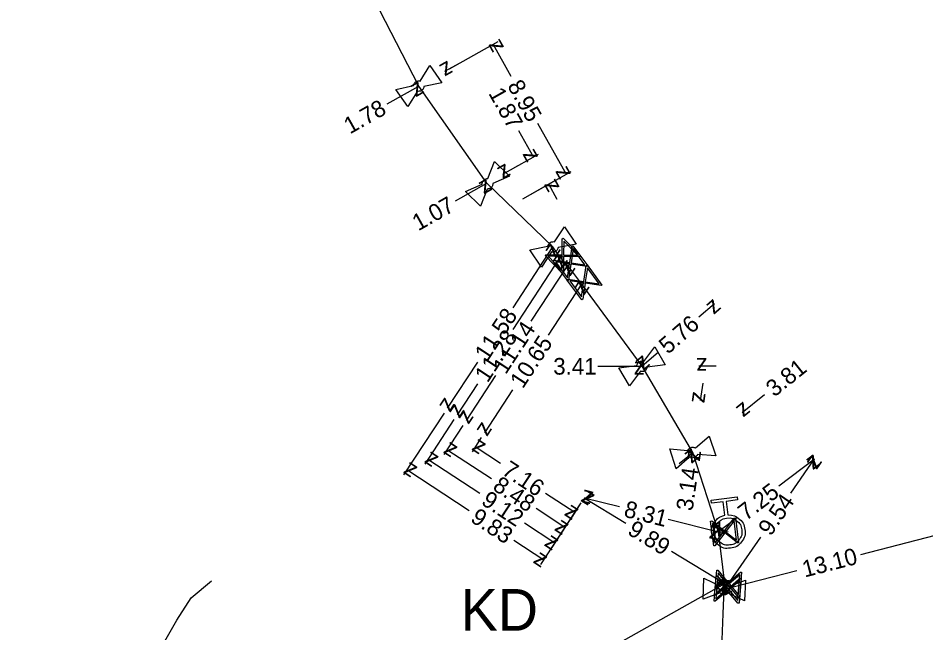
# Model space of a CAD drawing. Extents: x -638315 to -636370, y -1116147 to -1115110.
# Drawn here: x -637130.1 to -637075.6, y -1115916.4 to -1115879.5 of the extents above; entities that cross this region are included whole.
import ezdxf

# ---------------------------------------------------------------- set-up
doc = ezdxf.new("R2010")
doc.units = 0
for name, color, linetype in [('Default', 7, 'Continuous'), ('VP Hydrant', 7, 'Continuous'), ('VP Kótování', 7, 'Continuous'), ('VP Lomový bod', 7, 'Continuous'), ('VP Popis nerozlišený', 7, 'Continuous'), ('VP Přípojka', 7, 'Continuous'), ('VP Řad', 7, 'Continuous'), ('VP Šoupě', 7, 'Continuous')]:
    doc.layers.add(name, color=color, linetype=linetype)

msp = doc.modelspace()

# ---------------------------------------------------------------- linework, layer by layer
at = {"layer": 'Default'}
for points in [[(-637106.391, -1115883.58), (-637106.386, -1115883.527), (-637106.362, -1115883.478), (-637106.326, -1115883.402), (-637106.259, -1115883.355), (-637106.192, -1115883.308), (-637106.106, -1115883.299), (-637106.053, -1115883.293), (-637106.002, -1115883.307)], [(-637105.767, -1115883.642), (-637105.773, -1115883.693), (-637105.795, -1115883.742), (-637105.833, -1115883.819), (-637105.9, -1115883.866), (-637105.967, -1115883.913), (-637106.051, -1115883.921), (-637106.105, -1115883.927), (-637106.157, -1115883.913)], [(-637102.264, -1115889.505), (-637102.269, -1115889.453), (-637102.255, -1115889.4), (-637102.234, -1115889.318), (-637102.178, -1115889.259), (-637102.121, -1115889.2), (-637102.038, -1115889.175), (-637101.987, -1115889.16), (-637101.934, -1115889.163)], [(-637101.64, -1115889.447), (-637101.635, -1115889.498), (-637101.648, -1115889.55), (-637101.671, -1115889.634), (-637101.727, -1115889.693), (-637101.784, -1115889.752), (-637101.865, -1115889.776), (-637101.917, -1115889.791), (-637101.97, -1115889.788)], [(-637098.33, -1115893.221), (-637098.324, -1115893.168), (-637098.299, -1115893.119), (-637098.26, -1115893.044), (-637098.192, -1115892.999), (-637098.124, -1115892.954), (-637098.037, -1115892.948), (-637097.984, -1115892.944), (-637097.934, -1115892.959)], [(-637097.708, -1115893.3), (-637097.715, -1115893.351), (-637097.739, -1115893.399), (-637097.779, -1115893.475), (-637097.847, -1115893.521), (-637097.916, -1115893.566), (-637098, -1115893.571), (-637098.054, -1115893.575), (-637098.105, -1115893.561)], [(-637092.977, -1115900.374), (-637092.968, -1115900.322), (-637092.941, -1115900.275), (-637092.899, -1115900.202), (-637092.828, -1115900.161), (-637092.758, -1115900.119), (-637092.671, -1115900.118), (-637092.618, -1115900.116), (-637092.568, -1115900.134)], [(-637092.361, -1115900.486), (-637092.37, -1115900.537), (-637092.397, -1115900.584), (-637092.441, -1115900.658), (-637092.511, -1115900.699), (-637092.582, -1115900.741), (-637092.666, -1115900.742), (-637092.721, -1115900.743), (-637092.771, -1115900.726)], [(-637089.918, -1115905.479), (-637089.898, -1115905.43), (-637089.861, -1115905.39), (-637089.804, -1115905.328), (-637089.726, -1115905.303), (-637089.649, -1115905.278), (-637089.563, -1115905.295), (-637089.511, -1115905.306), (-637089.467, -1115905.333)], [(-637089.341, -1115905.723), (-637089.361, -1115905.77), (-637089.397, -1115905.81), (-637089.457, -1115905.873), (-637089.534, -1115905.898), (-637089.612, -1115905.923), (-637089.695, -1115905.906), (-637089.748, -1115905.895), (-637089.793, -1115905.867)], [(-637087.523, -1115909.35), (-637087.163, -1115909.334), (-637086.875, -1115909.56), (-637086.549, -1115909.814), (-637086.498, -1115910.227), (-637086.446, -1115910.638), (-637086.7, -1115910.964), (-637086.955, -1115911.29), (-637087.368, -1115911.342), (-637087.777, -1115911.393), (-637088.104, -1115911.14), (-637088.431, -1115910.887), (-637088.482, -1115910.476), (-637088.534, -1115910.063), (-637088.281, -1115909.736), (-637088.058, -1115909.444), (-637087.705, -1115909.373)], [(-637087.593, -1115909.542), (-637087.929, -1115909.584), (-637088.135, -1115909.849), (-637088.34, -1115910.114), (-637088.298, -1115910.449), (-637088.256, -1115910.784), (-637087.991, -1115910.99), (-637087.726, -1115911.196), (-637087.391, -1115911.154), (-637087.058, -1115911.112), (-637086.851, -1115910.847), (-637086.644, -1115910.582), (-637086.686, -1115910.247), (-637086.728, -1115909.912), (-637086.993, -1115909.706), (-637087.258, -1115909.5), (-637087.593, -1115909.542)], [(-637087.959, -1115913.621), (-637087.923, -1115913.584), (-637087.876, -1115913.559), (-637087.798, -1115913.521), (-637087.716, -1115913.525), (-637087.635, -1115913.529), (-637087.563, -1115913.573), (-637087.517, -1115913.602), (-637087.485, -1115913.644)], [(-637087.503, -1115914.051), (-637087.539, -1115914.09), (-637087.588, -1115914.115), (-637087.663, -1115914.153), (-637087.745, -1115914.149), (-637087.826, -1115914.146), (-637087.9, -1115914.099), (-637087.945, -1115914.072), (-637087.977, -1115914.03)]]:
    msp.add_open_spline(points, degree=3, dxfattribs=at)
at = {"layer": 'VP Hydrant'}
msp.add_lwpolyline([(-637087.705, -1115909.373), (-637087.807, -1115908.559), (-637088.491, -1115908.644), (-637088.514, -1115908.462), (-637086.964, -1115908.268), (-637086.941, -1115908.45), (-637087.625, -1115908.536), (-637087.523, -1115909.35)], dxfattribs=at)
at = {"layer": 'VP Kótování'}
for points in [[(-637104.226, -1115882.566), (-637101.311, -1115880.926)], [(-637100.524, -1115883.038), (-637101.616, -1115881.097)], [(-637103.616, -1115882.223), (-637104.531, -1115882.738)], [(-637107.971, -1115884.675), (-637106.08, -1115883.61)], [(-637098.949, -1115885.835), (-637097.225, -1115888.899)], [(-637100.085, -1115886.283), (-637099.193, -1115887.866)], [(-637100.75, -1115888.742), (-637098.888, -1115887.695)], [(-637100.14, -1115888.399), (-637101.055, -1115888.914)], [(-637099.835, -1115890.368), (-637096.92, -1115888.728)], [(-637099.835, -1115890.368), (-637097.973, -1115889.321)], [(-637103.865, -1115890.495), (-637101.99, -1115889.44)], [(-637097.764, -1115890.408), (-637098.278, -1115889.492)], [(-637100.419, -1115896.918), (-637098.02, -1115893.26)], [(-637100.416, -1115898.213), (-637097.592, -1115893.907)], [(-637099.324, -1115897.714), (-637097.135, -1115894.376)], [(-637098.298, -1115898.566), (-637096.292, -1115895.507)], [(-637089.262, -1115897.468), (-637088.32, -1115896.65)], [(-637091.708, -1115899.594), (-637092.67, -1115900.43)], [(-637102.562, -1115900.186), (-637104.373, -1115902.947)], [(-637095.321, -1115900.43), (-637092.67, -1115900.43)], [(-637088.21, -1115900.43), (-637089.26, -1115900.43)], [(-637101.468, -1115900.982), (-637103.242, -1115903.688)], [(-637102.559, -1115901.481), (-637103.777, -1115903.338)], [(-637100.442, -1115901.836), (-637102.134, -1115904.415)], [(-637089.03, -1115901.451), (-637089.18, -1115902.49)], [(-637085.312, -1115902.139), (-637086.66, -1115903.22)], [(-637104.565, -1115903.24), (-637106.991, -1115906.939)], [(-637103.969, -1115903.631), (-637105.726, -1115906.309)], [(-637103.434, -1115903.981), (-637104.583, -1115905.732)], [(-637102.326, -1115904.708), (-637102.882, -1115905.556)], [(-637101.722, -1115907.191), (-637104.391, -1115905.44)], [(-637101.171, -1115906.26), (-637102.69, -1115905.263)], [(-637090.449, -1115906.257), (-637089.63, -1115905.6)], [(-637102.407, -1115908.067), (-637105.534, -1115906.016)], [(-637084.453, -1115907.604), (-637082.32, -1115905.98)], [(-637083.737, -1115908.037), (-637082.32, -1115905.98)], [(-637103.055, -1115909.102), (-637106.799, -1115906.646)], [(-637098.46, -1115908.037), (-637096.706, -1115909.188)], [(-637093.65, -1115909.86), (-637096.15, -1115908.34)], [(-637094.035, -1115908.873), (-637096.15, -1115908.34)], [(-637099.039, -1115908.95), (-637097.299, -1115910.092)], [(-637096.342, -1115908.633), (-637098.768, -1115912.332)], [(-637096.342, -1115908.633), (-637098.098, -1115911.311)], [(-637096.342, -1115908.633), (-637097.491, -1115910.384)], [(-637096.342, -1115908.633), (-637096.898, -1115909.481)], [(-637087.007, -1115909.549), (-637088.089, -1115910.373)], [(-637099.724, -1115909.826), (-637097.907, -1115911.018)], [(-637091.094, -1115909.615), (-637088.089, -1115910.373)], [(-637079.528, -1115911.726), (-637075.04, -1115910.57)], [(-637100.372, -1115910.861), (-637098.576, -1115912.039)], [(-637085.556, -1115910.68), (-637087.73, -1115913.837)], [(-637090.908, -1115911.527), (-637087.7, -1115913.477)], [(-637083.367, -1115912.714), (-637087.73, -1115913.837)], [(-637096.537, -1115918.423), (-637087.7, -1115913.477)]]:
    msp.add_lwpolyline(points, dxfattribs=at)
at = {"layer": 'VP Lomový bod'}
for points in [[(-637106.002, -1115883.307), (-637105.415, -1115882.381)], [(-637105.415, -1115882.381), (-637104.698, -1115883.404), (-637105.767, -1115883.642)], [(-637106.157, -1115883.913), (-637106.744, -1115884.84), (-637107.462, -1115883.817), (-637106.391, -1115883.58)], [(-637101.934, -1115889.163), (-637101.536, -1115888.142)], [(-637101.536, -1115888.142), (-637100.635, -1115889.009), (-637101.64, -1115889.447)], [(-637101.97, -1115889.788), (-637102.369, -1115890.81), (-637103.27, -1115889.943), (-637102.264, -1115889.505)], [(-637097.934, -1115892.959), (-637097.322, -1115892.049)], [(-637097.322, -1115892.049), (-637096.632, -1115893.091), (-637097.708, -1115893.3)], [(-637098.105, -1115893.561), (-637098.718, -1115894.471), (-637099.407, -1115893.428), (-637098.33, -1115893.221)], [(-637092.568, -1115900.134), (-637091.909, -1115899.258)], [(-637091.909, -1115899.258), (-637091.276, -1115900.335), (-637092.361, -1115900.486)], [(-637092.771, -1115900.726), (-637093.431, -1115901.602), (-637094.064, -1115900.525), (-637092.977, -1115900.374)], [(-637089.467, -1115905.333), (-637088.633, -1115904.622)], [(-637088.633, -1115904.622), (-637088.249, -1115905.811), (-637089.341, -1115905.723)], [(-637089.793, -1115905.867), (-637090.628, -1115906.579), (-637091.012, -1115905.39), (-637089.918, -1115905.479)], [(-637089.007, -1115914.405), (-637088.951, -1115913.156), (-637087.959, -1115913.621)], [(-637087.485, -1115913.644), (-637086.454, -1115913.269), (-637086.51, -1115914.518), (-637087.503, -1115914.051)], [(-637087.977, -1115914.03), (-637089.007, -1115914.405)]]:
    msp.add_lwpolyline(points, dxfattribs=at)
at = {"layer": 'VP Přípojka'}
for points in [[(-637097.592, -1115893.907), (-637097.43, -1115893.79)], [(-637097.135, -1115894.376), (-637096.98, -1115894.25)], [(-637096.292, -1115895.507), (-637096.13, -1115895.39)], [(-637088.089, -1115910.373), (-637087.789, -1115910.377), (-637087.49, -1115910.35)], [(-637130.14, -1115939.39), (-637130.073, -1115939.252), (-637126.46, -1115931.82), (-637123.79, -1115922.17), (-637122.22, -1115918.47), (-637120.62, -1115915.67), (-637119.74, -1115914.32), (-637118.52, -1115913.31)], [(-637087.73, -1115913.837), (-637087.53, -1115913.84)], [(-637087.7, -1115913.477), (-637087.5, -1115913.48)]]:
    msp.add_lwpolyline(points, dxfattribs=at)
at = {"layer": 'VP Řad'}
msp.add_lwpolyline([(-637094.23, -1115955.262), (-637093.49, -1115944.54), (-637091.91, -1115936.71), (-637089.3, -1115926.72), (-637089.319, -1115926.747), (-637087.994, -1115918.056), (-637087.889, -1115917.367), (-637087.796, -1115915.284), (-637087.73, -1115913.837), (-637087.7, -1115913.477), (-637088.089, -1115910.373), (-637089.63, -1115905.6), (-637092.67, -1115900.43), (-637096.292, -1115895.507), (-637097.135, -1115894.376), (-637097.592, -1115893.907), (-637098.02, -1115893.26), (-637101.99, -1115889.44), (-637106.08, -1115883.61), (-637108.074, -1115879.731), (-637111.304, -1115873.45)], dxfattribs=at)
at = {"layer": 'VP Šoupě'}
for points in [[(-637097.417, -1115892.73), (-637096.37, -1115893.804), (-637096.417, -1115893.85), (-637096.545, -1115893.844), (-637097.385, -1115893.835), (-637097.397, -1115894.805), (-637097.444, -1115894.851), (-637098.491, -1115893.777), (-637098.444, -1115893.731), (-637097.472, -1115893.745), (-637097.462, -1115892.905), (-637097.464, -1115892.776), (-637097.417, -1115892.73)], [(-637096.827, -1115893.201), (-637095.93, -1115894.404), (-637095.983, -1115894.443), (-637096.11, -1115894.42), (-637096.941, -1115894.3), (-637097.08, -1115895.261), (-637097.133, -1115895.3), (-637098.029, -1115894.097), (-637097.977, -1115894.058), (-637097.015, -1115894.2), (-637096.895, -1115893.369), (-637096.88, -1115893.24), (-637096.827, -1115893.201)], [(-637097.374, -1115892.908), (-637097.384, -1115893.746), (-637096.547, -1115893.756), (-637097.374, -1115892.908)], [(-637096.808, -1115893.383), (-637096.928, -1115894.213), (-637096.1, -1115894.333), (-637096.808, -1115893.383)], [(-637097.483, -1115894.676), (-637097.473, -1115893.833), (-637098.314, -1115893.824), (-637097.483, -1115894.676)], [(-637097.149, -1115895.122), (-637097.028, -1115894.287), (-637097.861, -1115894.167), (-637097.149, -1115895.122)], [(-637095.971, -1115894.342), (-637095.082, -1115895.55), (-637095.135, -1115895.589), (-637095.261, -1115895.566), (-637096.092, -1115895.44), (-637096.237, -1115896.4), (-637096.29, -1115896.439), (-637097.179, -1115895.231), (-637097.126, -1115895.192), (-637096.166, -1115895.34), (-637096.04, -1115894.509), (-637096.024, -1115894.381), (-637095.971, -1115894.342)], [(-637095.953, -1115894.524), (-637096.079, -1115895.353), (-637095.251, -1115895.478), (-637095.953, -1115894.524)], [(-637096.305, -1115896.261), (-637096.179, -1115895.427), (-637097.011, -1115895.301), (-637096.305, -1115896.261)], [(-637087.067, -1115909.533), (-637086.881, -1115911.021), (-637086.946, -1115911.03), (-637087.045, -1115910.948), (-637087.709, -1115910.433), (-637088.304, -1115911.2), (-637088.369, -1115911.208), (-637088.556, -1115909.72), (-637088.49, -1115909.711), (-637087.724, -1115910.309), (-637087.21, -1115909.645), (-637087.133, -1115909.541), (-637087.067, -1115909.533)], [(-637088.295, -1115911.045), (-637087.778, -1115910.379), (-637088.443, -1115909.864), (-637088.295, -1115911.045)], [(-637087.141, -1115909.701), (-637087.655, -1115910.363), (-637086.993, -1115910.876), (-637087.141, -1115909.701)], [(-637086.691, -1115912.795), (-637086.815, -1115914.29), (-637086.881, -1115914.284), (-637086.961, -1115914.183), (-637087.504, -1115913.543), (-637088.244, -1115914.17), (-637088.31, -1115914.165), (-637088.185, -1115912.67), (-637088.12, -1115912.676), (-637087.494, -1115913.419), (-637086.853, -1115912.875), (-637086.756, -1115912.789), (-637086.691, -1115912.795)], [(-637088.204, -1115914.021), (-637087.561, -1115913.476), (-637088.105, -1115912.834), (-637088.204, -1115914.021)], [(-637086.72, -1115913.155), (-637086.844, -1115914.65), (-637086.91, -1115914.644), (-637086.99, -1115914.543), (-637087.533, -1115913.903), (-637088.273, -1115914.53), (-637088.339, -1115914.525), (-637088.214, -1115913.03), (-637088.149, -1115913.036), (-637087.523, -1115913.779), (-637086.882, -1115913.235), (-637086.785, -1115913.149), (-637086.72, -1115913.155)], [(-637088.233, -1115914.381), (-637087.59, -1115913.836), (-637088.134, -1115913.194), (-637088.233, -1115914.381)], [(-637086.826, -1115913.304), (-637087.466, -1115913.846), (-637086.924, -1115914.484), (-637086.826, -1115913.304)], [(-637086.797, -1115912.944), (-637087.437, -1115913.486), (-637086.895, -1115914.124), (-637086.797, -1115912.944)]]:
    msp.add_lwpolyline(points, dxfattribs=at)

# ---------------------------------------------------------------- texts
at = {"layer": 'VP Kótování'}
for s, rotation, p in [('z', 119.371, (-637100.935, -1115881.288)), ('z', 209.3771, (-637104.341, -1115882.057)), ('z', 29.3771, (-637106.27, -1115884.291)), ('8.95', 299.371, (-637100.788, -1115883.588)), ('1.87', 299.3678, (-637101.922, -1115884.037)), ('1.78', 29.3771, (-637110.217, -1115886.513)), ('z', 299.3678, (-637099.874, -1115887.676)), ('z', 209.3607, (-637100.864, -1115888.233)), ('z', 299.371, (-637097.906, -1115888.709)), ('z', 29.3606, (-637102.181, -1115890.121)), ('z', 119.3678, (-637097.598, -1115889.683)), ('1.07', 29.3606, (-637106.111, -1115892.332)), ('z', 56.742, (-637097.876, -1115893.952)), ('z', 56.7425, (-637097.448, -1115894.599)), ('z', 56.7423, (-637096.991, -1115895.068)), ('z', 56.7425, (-637096.148, -1115896.199)), ('z', 40.9895, (-637088.369, -1115897.355)), ('11.58', 56.742, (-637101.952, -1115900.167)), ('5.76', 40.9895, (-637091.116, -1115899.742)), ('11.14', 56.7423, (-637100.858, -1115900.964)), ('11.28', 56.7425, (-637101.949, -1115901.462)), ('10.65', 56.7425, (-637099.832, -1115901.817)), ('z', 220.9895, (-637092.621, -1115899.725)), ('z', 180, (-637088.76, -1115899.93)), ('3.81', 38.7069, (-637084.726, -1115902.311)), ('z', 236.7421, (-637104.517, -1115902.255)), ('z', 261.7667, (-637089.603, -1115901.924)), ('z', 236.7425, (-637103.921, -1115902.646)), ('z', 218.7068, (-637086.582, -1115902.517)), ('z', 236.7423, (-637103.386, -1115902.996)), ('z', 236.7425, (-637102.278, -1115903.723)), ('z', 146.7371, (-637103.699, -1115905.296)), ('z', 146.7385, (-637101.998, -1115905.119)), ('z', 146.742, (-637104.841, -1115905.872)), ('z', 38.7069, (-637089.708, -1115906.303)), ('z', 81.7667, (-637089.207, -1115906.166)), ('z', 37.2887, (-637082.415, -1115906.681)), ('z', 55.4503, (-637082.192, -1115906.675)), ('z', 146.7414, (-637106.107, -1115906.502)), ('7.16', 326.7385, (-637101.152, -1115906.87)), ('3.14', 81.7667, (-637089.639, -1115909.152)), ('8.48', 326.7371, (-637101.703, -1115907.801)), ('z', 148.7033, (-637095.463, -1115908.172)), ('z', 165.8451, (-637095.543, -1115907.977)), ('7.25', 37.2887, (-637086.426, -1115909.735)), ('9.12', 326.742, (-637102.389, -1115908.677)), ('9.54', 55.4503, (-637084.946, -1115910.675)), ('9.83', 326.7414, (-637103.037, -1115909.712)), ('z', 326.7385, (-637097.398, -1115909.332)), ('8.31', 345.8451, (-637093.818, -1115909.444)), ('z', 326.7371, (-637097.991, -1115910.236)), ('9.89', 328.7034, (-637093.61, -1115910.469)), ('z', 345.8451, (-637088.696, -1115910.736)), ('z', 217.2887, (-637087.994, -1115909.672)), ('z', 326.742, (-637098.599, -1115911.162)), ('z', 326.7414, (-637099.269, -1115912.183)), ('13.10', 14.4371, (-637082.904, -1115913.111)), ('z', 328.7034, (-637088.387, -1115913.645)), ('z', 235.4503, (-637087.858, -1115913.142)), ('z', 29.236, (-637087.892, -1115914.158)), ('z', 194.4371, (-637087.37, -1115913.228))]:
    msp.add_text(s, height=1, rotation=rotation, dxfattribs=at).set_placement(p)
for s, p in [('3.41', (-637098.004, -1115900.93)), ('z', (-637093.17, -1115900.93))]:
    msp.add_text(s, height=1, dxfattribs=at).set_placement(p)
at = {"layer": 'VP Popis nerozlišený'}
msp.add_text('KD', height=2.5, dxfattribs=at).set_placement((-637103.563, -1115916.3))

doc.saveas('drawing.dxf')
